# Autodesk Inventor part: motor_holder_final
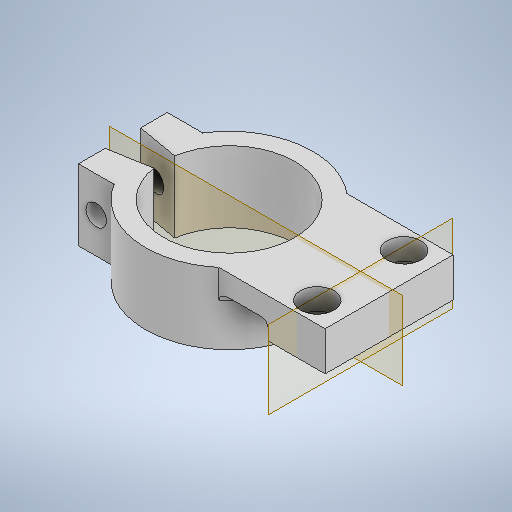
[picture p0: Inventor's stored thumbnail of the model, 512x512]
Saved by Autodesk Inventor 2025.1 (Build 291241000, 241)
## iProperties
Created: 2024-11
Part Number: motor_holder_final
Material: Generic
Document SubType Name: Modeling
Designer: mansa
Density: 1 g/cm^3
Appearance: Default
Author: mansa
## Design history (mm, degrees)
derived "motor_holder_ass.iam"
fillet "Fillet1" dims "d1" = 2
workplane "Work Plane1"
workplane "Work Plane2"
body "Solid1"
node "basic_frame_screw_mount.ipt:1" dims "d0" = 10
node "motor holder_v2.ipt:1" dims "d0" = 10
node "motor_holder_ass.iam_Bodies" dims "d0" = 10
